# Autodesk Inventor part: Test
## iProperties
Created: 2007-03
Part Number: Test
Cost Center: 259021.06 kg
Document SubType Name: Modeling
Designer: M. Mafli
Authority: 259021063450.5 mm^3
TotalMass: 259021.06 kg
TotalVolume: 259021063450.5 mm^3
Author: M. Mafli
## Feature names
1. Extrusion1
2. Extrusion2
